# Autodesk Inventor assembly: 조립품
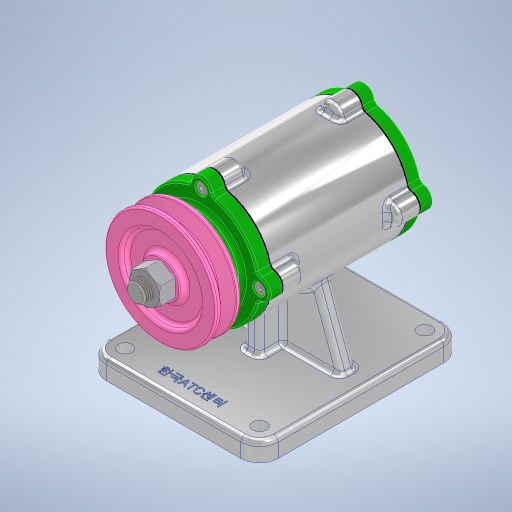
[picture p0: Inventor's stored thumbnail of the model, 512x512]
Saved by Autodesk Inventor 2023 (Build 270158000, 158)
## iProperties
Created: 2023-08
Part Number: 조립품
Document SubType Name: Assembly
Designer: asung
Author: asung
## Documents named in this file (12)
- C:\Users\asung\Desktop\730808V1011\조립품.iam
- C:\Users\asung\Desktop\730808V1011\본체.ipt
- C:\Users\asung\Desktop\730808V1011\베어링 6204.ipt
- C:\Users\asung\Desktop\730808V1011\축.ipt
- C:\Users\asung\Desktop\730808V1011\개스킷.ipt
- C:\Users\asung\Desktop\730808V1011\앞커버.ipt
- C:\Users\asung\Desktop\730808V1011\뒤커버.ipt
- C:\Users\asung\Desktop\730808V1011\오일 실.ipt
- C:\Users\asung\Desktop\730808V1011\키 4 x 4.ipt
- C:\Users\asung\Desktop\730808V1011\V-벨트풀리.ipt
- C:\Users\asung\Desktop\730808V1011\볼트 M4 x 12.ipt
- C:\Users\asung\Desktop\730808V1011\너트 M12 x 1.25.ipt
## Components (8 placed, 6 different names)
1. KS B 2023 6204 - 20 x 47 x 14:1
2. KS B 2023 6204 - 20 x 47 x 14:2
3. 개스킷:1
4. 개스킷:2
5. KS B 2804 D D - 20 32 8:1
6. KS B 1311 (I) 4 x 4 x 12:1
7. V-벨트풀리:1
8. KS B 1012 클래스 1 일반 - 미터 M12x1.25:1
